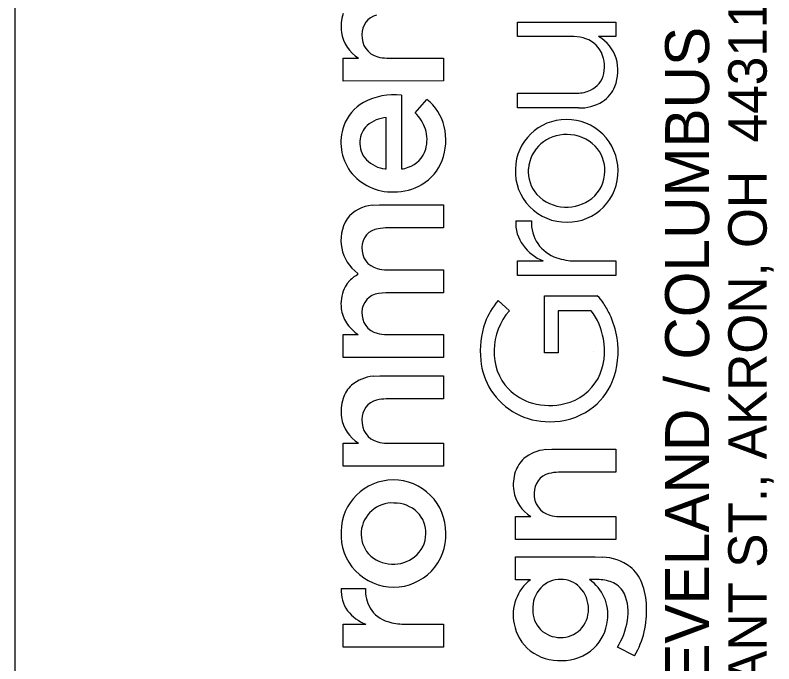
# Model space of a CAD drawing. Extents: x 0 to 70.6, y 0 to 31.9.
# Drawn here: x 32 to 32.984, y 3.594 to 4.436 of the extents above; entities that cross this region are included whole.
import ezdxf

# ---------------------------------------------------------------- set-up
doc = ezdxf.new("R2010")
doc.units = 0
doc.layers.add('GM_X_County', color=7, linetype='Continuous')
doc.layers.add('GM_X_Township', color=7, linetype='Continuous')

msp = doc.modelspace()

# ---------------------------------------------------------------- linework, layer by layer
at = {"layer": 'GM_X_County'}
msp.add_line((32, 0.5), (32, 21.5), dxfattribs=at)
at = {"layer": 'GM_X_Township'}
for p, q in [((32.65152, 4.40801), (32.65153, 4.42672)), ((32.65153, 4.42672), (32.7791, 4.42664)), ((32.7791, 4.42664), (32.77908, 4.40796)), ((32.7249, 4.40796), (32.65152, 4.40801)), ((32.7328, 4.40727), (32.7249, 4.40796)), ((32.77908, 4.40796), (32.75689, 4.40796)), ((32.42542, 4.38016), (32.44552, 4.38021)), ((32.42542, 4.35035), (32.42542, 4.38016)), ((32.48222, 4.38021), (32.55569, 4.38021)), ((32.55569, 4.38021), (32.55571, 4.35045)), ((32.55571, 4.35045), (32.42542, 4.35035)), ((32.50108, 4.33209), (32.50118, 4.23657)), ((32.65154, 4.33443), (32.72905, 4.3345)), ((32.65165, 4.31543), (32.65154, 4.33443)), ((32.51882, 4.30927), (32.53422, 4.32662)), ((32.73073, 4.31543), (32.65165, 4.31543)), ((32.48144, 4.23644), (32.48144, 4.30296)), ((32.48016, 4.23628), (32.48144, 4.23644)), ((32.46329, 4.18915), (32.47259, 4.18968)), ((32.47259, 4.18968), (32.55557, 4.18968)), ((32.55557, 4.18968), (32.55571, 4.15982)), ((32.64932, 4.16907), (32.66978, 4.16907)), ((32.48058, 4.15981), (32.47102, 4.15881)), ((32.55571, 4.15982), (32.48058, 4.15981)), ((32.65152, 4.11699), (32.68476, 4.117)), ((32.65152, 4.098), (32.65152, 4.11699)), ((32.72605, 4.11703), (32.7791, 4.11696)), ((32.7791, 4.11696), (32.77903, 4.098)), ((32.48218, 4.10553), (32.55571, 4.10548)), ((32.55571, 4.10548), (32.55571, 4.07568)), ((32.44443, 4.09922), (32.44455, 4.10072)), ((32.77903, 4.098), (32.65152, 4.098)), ((32.4809, 4.07567), (32.47143, 4.07474)), ((32.55571, 4.07568), (32.4809, 4.07567)), ((32.62636, 4.06548), (32.64114, 4.05241)), ((32.6868, 4.07185), (32.75516, 4.07192)), ((32.6868, 3.99778), (32.6868, 4.07185)), ((32.70448, 4.05241), (32.70432, 3.99775)), ((32.74737, 4.05227), (32.70448, 4.05241)), ((32.42542, 3.99152), (32.42545, 4.02138)), ((32.42545, 4.02138), (32.44515, 4.02138)), ((32.48206, 4.02138), (32.55571, 4.02136)), ((32.55571, 4.02136), (32.55571, 3.99156)), ((32.70432, 3.99775), (32.6868, 3.99778)), ((32.75, 4), (32.75, 4)), ((32.55571, 3.99156), (32.42542, 3.99152)), ((32.46439, 3.96736), (32.47289, 3.96783)), ((32.47289, 3.96783), (32.55571, 3.96783)), ((32.55571, 3.96783), (32.55571, 3.93804)), ((32.55571, 3.93804), (32.4814, 3.93796)), ((32.42542, 3.88066), (32.44552, 3.88071)), ((32.42542, 3.85086), (32.42542, 3.88066)), ((32.48222, 3.88071), (32.55569, 3.88071)), ((32.55569, 3.88071), (32.55571, 3.85096)), ((32.68784, 3.8722), (32.69634, 3.87266)), ((32.69634, 3.87266), (32.77916, 3.87266)), ((32.77916, 3.87266), (32.77917, 3.84287)), ((32.55571, 3.85096), (32.42542, 3.85086)), ((32.77917, 3.84287), (32.70485, 3.8428)), ((32.64888, 3.7855), (32.66897, 3.78555)), ((32.64888, 3.75569), (32.64888, 3.7855)), ((32.70568, 3.78555), (32.77915, 3.78555)), ((32.77915, 3.78555), (32.77917, 3.75579)), ((32.77917, 3.75579), (32.64888, 3.75569)), ((32.6489, 3.70336), (32.64889, 3.73322)), ((32.64889, 3.73322), (32.75236, 3.73322)), ((32.75236, 3.73322), (32.76191, 3.73285)), ((32.66836, 3.70336), (32.6489, 3.70336)), ((32.75763, 3.70356), (32.74487, 3.70361)), ((32.42299, 3.69193), (32.45454, 3.69193)), ((32.42542, 3.64577), (32.45473, 3.64579)), ((32.42542, 3.61593), (32.42542, 3.64577)), ((32.50413, 3.64581), (32.55571, 3.64573)), ((32.55571, 3.64573), (32.55565, 3.61593)), ((32.55565, 3.61593), (32.42542, 3.61593)), ((32.8036, 3.60491), (32.7812, 3.61598))]:
    msp.add_line(p, q, dxfattribs=at)
for points in [[(32.7328, 4.40727), (32.7249, 4.40796), (32.65152, 4.40801), (32.65153, 4.42672), (32.7791, 4.42664), (32.77908, 4.40796), (32.75689, 4.40796)], [(32.42542, 4.35035), (32.42542, 4.38016), (32.44552, 4.38021)], [(32.48222, 4.38021), (32.55569, 4.38021), (32.55571, 4.35045), (32.42542, 4.35035)], [(32.50108, 4.33209), (32.50118, 4.23657)], [(32.73073, 4.31543), (32.65165, 4.31543), (32.65154, 4.33443), (32.72905, 4.3345)], [(32.51882, 4.30927), (32.53422, 4.32662)], [(32.48016, 4.23628), (32.48144, 4.23644), (32.48144, 4.30296)], [(32.46329, 4.18915), (32.47259, 4.18968), (32.55557, 4.18968), (32.55571, 4.15982), (32.48058, 4.15981), (32.47102, 4.15881)], [(32.64932, 4.16907), (32.66978, 4.16907)], [(32.72605, 4.11703), (32.7791, 4.11696), (32.77903, 4.098), (32.65152, 4.098)], [(32.65152, 4.098), (32.65152, 4.11699), (32.68476, 4.117)], [(32.48218, 4.10553), (32.55571, 4.10548), (32.55571, 4.07568), (32.4809, 4.07567), (32.47143, 4.07474)], [(32.44443, 4.09922), (32.44455, 4.10072)], [(32.62636, 4.06548), (32.64114, 4.05241)], [(32.74737, 4.05227), (32.70448, 4.05241), (32.70432, 3.99775), (32.6868, 3.99778), (32.6868, 4.07185), (32.75516, 4.07192)], [(32.42542, 3.99152), (32.42545, 4.02138), (32.44515, 4.02138)], [(32.48206, 4.02138), (32.55571, 4.02136), (32.55571, 3.99156), (32.42542, 3.99152)], [(32.46439, 3.96736), (32.47289, 3.96783), (32.55571, 3.96783), (32.55571, 3.93804), (32.4814, 3.93796)], [(32.42542, 3.85086), (32.42542, 3.88066), (32.44552, 3.88071)], [(32.48222, 3.88071), (32.55569, 3.88071), (32.55571, 3.85096), (32.42542, 3.85086)], [(32.68784, 3.8722), (32.69634, 3.87266), (32.77916, 3.87266), (32.77917, 3.84287), (32.70485, 3.8428)], [(32.64888, 3.75569), (32.64888, 3.7855), (32.66897, 3.78555)], [(32.70568, 3.78555), (32.77915, 3.78555), (32.77917, 3.75579), (32.64888, 3.75569)], [(32.66836, 3.70336), (32.6489, 3.70336), (32.64889, 3.73322), (32.75236, 3.73322), (32.76191, 3.73285)], [(32.75763, 3.70356), (32.74487, 3.70361)], [(32.42299, 3.69193), (32.45454, 3.69193)], [(32.50413, 3.64581), (32.55571, 3.64573), (32.55565, 3.61593), (32.42542, 3.61593)], [(32.42542, 3.61593), (32.42542, 3.64577), (32.45473, 3.64579)], [(32.8036, 3.60491), (32.7812, 3.61598)]]:
    msp.add_lwpolyline(points, dxfattribs=at)
for centre, radius, start, end in [((32.47872, 4.42108), 0.05602, 162.27398, 187.79173), ((32.47872, 4.42108), 0.05602, 162.27398, 187.79173), ((32.47482, 4.41155), 0.02498, 103.68683, 182.21395), ((32.47482, 4.41155), 0.02498, 103.68683, 182.21395), ((32.47027, 4.4209), 0.04763, 188.96462, 238.69865), ((32.47027, 4.4209), 0.04763, 188.96462, 238.69865), ((32.47735, 4.40846), 0.02757, 175.58441, 255.13816), ((32.47735, 4.40846), 0.02757, 175.58441, 255.13816), ((32.72711, 4.36998), 0.03772, 33.50082, 81.32954), ((32.72711, 4.36998), 0.03772, 33.50082, 81.32954), ((32.73239, 4.36485), 0.04959, 17.62209, 60.38974), ((32.73239, 4.36485), 0.04959, 17.62209, 60.38974), ((32.72414, 4.3695), 0.04048, 346.56179, 31.75389), ((32.72414, 4.3695), 0.04048, 346.56179, 31.75389), ((32.48183, 4.42235), 0.04215, 254.08913, 270.52838), ((32.48183, 4.42235), 0.04215, 254.08913, 270.52838), ((32.72343, 4.36415), 0.05838, 339.16197, 15.61485), ((32.72343, 4.36415), 0.05838, 339.16197, 15.61485), ((32.73371, 4.36616), 0.03042, 294.63214, 348.48625), ((32.73371, 4.36616), 0.03042, 294.63214, 348.48625), ((32.739, 4.35901), 0.04201, 303.10391, 338.15613), ((32.739, 4.35901), 0.04201, 303.10391, 338.15613), ((32.49176, 4.24874), 0.08387, 83.62118, 118.28448), ((32.49176, 4.24874), 0.08387, 83.62118, 118.28448), ((32.72747, 4.38081), 0.04633, 271.95199, 294.08943), ((32.72747, 4.38081), 0.04633, 271.95199, 294.08943), ((32.47894, 4.27368), 0.05583, 118.82935, 160.62242), ((32.47894, 4.27368), 0.05583, 118.82935, 160.62242), ((32.49399, 4.2763), 0.06443, 13.53275, 51.36266), ((32.49399, 4.2763), 0.06443, 13.53275, 51.36266), ((32.7321, 4.37256), 0.05715, 268.62699, 301.47779), ((32.7321, 4.37256), 0.05715, 268.62699, 301.47779), ((32.4844, 4.26071), 0.04236, 94.01311, 130.88062), ((32.4844, 4.26071), 0.04236, 94.01311, 130.88062), ((32.48033, 4.27018), 0.05485, 19.0387, 45.44322), ((32.48033, 4.27018), 0.05485, 19.0387, 45.44322), ((32.48697, 4.27074), 0.06438, 160.52138, 215.78155), ((32.48697, 4.27074), 0.06438, 160.52138, 215.78155), ((32.47703, 4.2709), 0.02985, 132.98553, 177.1802), ((32.47703, 4.2709), 0.02985, 132.98553, 177.1802), ((32.48289, 4.27384), 0.0758, 339.35431, 13.37708), ((32.48289, 4.27384), 0.0758, 339.35431, 13.37708), ((32.71435, 4.23484), 0.06552, 89.48213, 178.77752), ((32.71435, 4.23484), 0.06552, 89.48213, 178.77752), ((32.71582, 4.23414), 0.06623, 0.42265, 90.7613), ((32.71582, 4.23414), 0.06623, 0.42265, 90.7613), ((32.48724, 4.27433), 0.04701, 344.60723, 17.00675), ((32.48724, 4.27433), 0.04701, 344.60723, 17.00675), ((32.47824, 4.26966), 0.03114, 175.00138, 223.2876), ((32.47824, 4.26966), 0.03114, 175.00138, 223.2876), ((32.71397, 4.23244), 0.04846, 87.68827, 175.01696), ((32.71397, 4.23244), 0.04846, 87.68827, 175.01696), ((32.71659, 4.23036), 0.05052, 44.91202, 90.75914), ((32.71659, 4.23036), 0.05052, 44.91202, 90.75914), ((32.49895, 4.27177), 0.03504, 288.01084, 343.55364), ((32.49895, 4.27177), 0.03504, 288.01084, 343.55364), ((32.71955, 4.23452), 0.04549, 358.32279, 43.83486), ((32.71955, 4.23452), 0.04549, 358.32279, 43.83486), ((32.48546, 4.27826), 0.04232, 225.06454, 262.79701), ((32.48546, 4.27826), 0.04232, 225.06454, 262.79701), ((32.49548, 4.26982), 0.0626, 300.94393, 338.73223), ((32.49548, 4.26982), 0.0626, 300.94393, 338.73223), ((32.48908, 4.27516), 0.06872, 217.74341, 271.65606), ((32.48908, 4.27516), 0.06872, 217.74341, 271.65606), ((32.50129, 4.25678), 0.02021, 269.70042, 294.87295), ((32.50129, 4.25678), 0.02021, 269.70042, 294.87295), ((32.71483, 4.2334), 0.06606, 177.53728, 270.94524), ((32.71483, 4.2334), 0.06606, 177.53728, 270.94524), ((32.71085, 4.23311), 0.0453, 175.51467, 221.42047), ((32.71085, 4.23311), 0.0453, 175.51467, 221.42047), ((32.71671, 4.23271), 0.06536, 269.30834, 1.67905), ((32.71671, 4.23271), 0.06536, 269.30834, 1.67905), ((32.71931, 4.23374), 0.04572, 308.90382, 359.30947), ((32.71931, 4.23374), 0.04572, 308.90382, 359.30947), ((32.49204, 4.27702), 0.07055, 269.20529, 300.33566), ((32.49204, 4.27702), 0.07055, 269.20529, 300.33566), ((32.71399, 4.23734), 0.05046, 222.66255, 268.37331), ((32.71399, 4.23734), 0.05046, 222.66255, 268.37331), ((32.71567, 4.23859), 0.05178, 266.55312, 308.67253), ((32.71567, 4.23859), 0.05178, 266.55312, 308.67253), ((32.46638, 4.14404), 0.04521, 93.91118, 142.30723), ((32.46638, 4.14404), 0.04521, 93.91118, 142.30723), ((32.47585, 4.14373), 0.05319, 148.28793, 233.9556), ((32.47585, 4.14373), 0.05319, 148.28793, 233.9556), ((32.69878, 4.16662), 0.04952, 177.16211, 216.28024), ((32.69878, 4.16662), 0.04952, 177.16211, 216.28024), ((32.71735, 4.16638), 0.04764, 176.76988, 252.15044), ((32.71735, 4.16638), 0.04764, 176.76988, 252.15044), ((32.47384, 4.13499), 0.02399, 96.75763, 181.6251), ((32.47384, 4.13499), 0.02399, 96.75763, 181.6251), ((32.47577, 4.13241), 0.02597, 175.81573, 256.16716), ((32.47577, 4.13241), 0.02597, 175.81573, 256.16716), ((32.70975, 4.17555), 0.06366, 216.91526, 246.88619), ((32.70975, 4.17555), 0.06366, 216.91526, 246.88619), ((32.7269, 4.19175), 0.07473, 251.13884, 269.34694), ((32.7269, 4.19175), 0.07473, 251.13884, 269.34694), ((32.4817, 4.15053), 0.04501, 254.34629, 270.61033), ((32.4817, 4.15053), 0.04501, 254.34629, 270.61033), ((32.4638, 4.06267), 0.04137, 117.91625, 139.24296), ((32.4638, 4.06267), 0.04137, 117.91625, 139.24296), ((32.46194, 4.06452), 0.03875, 139.52447, 154.84698), ((32.46194, 4.06452), 0.03875, 139.52447, 154.84698), ((32.47144, 4.0612), 0.04877, 156.06382, 187.3493), ((32.47144, 4.0612), 0.04877, 156.06382, 187.3493), ((32.47421, 4.05056), 0.02434, 96.5532, 179.94902), ((32.47421, 4.05056), 0.02434, 96.5532, 179.94902), ((32.70163, 4.00187), 0.09855, 139.79476, 159.13696), ((32.70163, 4.00187), 0.09855, 139.79476, 159.13696), ((32.72498, 4.03937), 0.04438, 30.98913, 47.16099), ((32.72498, 4.03937), 0.04438, 30.98913, 47.16099), ((32.46461, 4.05974), 0.04181, 186.5579, 213.38846), ((32.46461, 4.05974), 0.04181, 186.5579, 213.38846), ((32.67091, 4.00018), 0.11106, 25.30315, 33.96179), ((32.67091, 4.00018), 0.11106, 25.30315, 33.96179), ((32.47608, 4.04863), 0.02628, 175.722, 255.78627), ((32.47608, 4.04863), 0.02628, 175.722, 255.78627), ((32.69899, 4.00079), 0.07753, 138.25804, 179.70064), ((32.69899, 4.00079), 0.07753, 138.25804, 179.70064), ((32.67889, 4.00099), 0.08556, 10.07509, 36.83189), ((32.67889, 4.00099), 0.08556, 10.07509, 36.83189), ((32.6704, 3.99987), 0.11166, 8.80339, 25.33484), ((32.6704, 3.99987), 0.11166, 8.80339, 25.33484), ((32.47886, 4.07078), 0.0598, 214.70433, 235.68724), ((32.47886, 4.07078), 0.0598, 214.70433, 235.68724), ((32.7187, 3.99968), 0.11536, 161.14379, 185.62812), ((32.7187, 3.99968), 0.11536, 161.14379, 185.62812), ((32.48195, 4.06518), 0.0438, 253.66719, 270.14979), ((32.48195, 4.06518), 0.0438, 253.66719, 270.14979), ((32.68425, 4.00057), 0.08036, 333.46689, 11.03668), ((32.68425, 4.00057), 0.08036, 333.46689, 11.03668), ((32.67564, 3.99977), 0.10649, 338.28866, 9.28548), ((32.67564, 3.99977), 0.10649, 338.28866, 9.28548), ((32.68811, 3.99732), 0.06676, 176.66577, 223.6912), ((32.68811, 3.99732), 0.06676, 176.66577, 223.6912), ((32.69336, 3.99699), 0.08987, 185.50773, 212.01294), ((32.69336, 3.99699), 0.08987, 185.50773, 212.01294), ((32.46871, 3.91767), 0.04988, 94.97056, 130.22484), ((32.46871, 3.91767), 0.04988, 94.97056, 130.22484), ((32.69868, 3.99547), 0.0652, 282.88151, 331.81475), ((32.69868, 3.99547), 0.0652, 282.88151, 331.81475), ((32.69835, 3.99168), 0.08241, 305.03061, 337.67573), ((32.69835, 3.99168), 0.08241, 305.03061, 337.67573), ((32.46348, 3.92602), 0.04016, 132.22383, 161.68229), ((32.46348, 3.92602), 0.04016, 132.22383, 161.68229), ((32.69211, 3.99748), 0.08908, 212.70222, 270.71399), ((32.69211, 3.99748), 0.08908, 212.70222, 270.71399), ((32.69045, 4.00011), 0.07039, 224.02147, 253.88), ((32.69045, 4.00011), 0.07039, 224.02147, 253.88), ((32.47872, 3.92158), 0.05602, 162.27398, 187.79173), ((32.47872, 3.92158), 0.05602, 162.27398, 187.79173), ((32.48108, 3.89196), 0.04601, 89.60515, 105.33026), ((32.48108, 3.89196), 0.04601, 89.60515, 105.33026), ((32.47482, 3.91206), 0.02498, 103.68683, 182.21395), ((32.47482, 3.91206), 0.02498, 103.68683, 182.21395), ((32.69318, 4.01254), 0.08309, 254.45353, 283.9512), ((32.69318, 4.01254), 0.08309, 254.45353, 283.9512), ((32.69429, 3.99979), 0.09138, 269.3273, 304.19632), ((32.69429, 3.99979), 0.09138, 269.3273, 304.19632), ((32.47027, 3.92141), 0.04763, 188.96462, 238.69865), ((32.47027, 3.92141), 0.04763, 188.96462, 238.69865), ((32.47735, 3.90897), 0.02757, 175.58441, 255.13816), ((32.47735, 3.90897), 0.02757, 175.58441, 255.13816), ((32.48183, 3.92286), 0.04215, 254.08913, 270.52838), ((32.48183, 3.92286), 0.04215, 254.08913, 270.52838), ((32.69216, 3.82251), 0.04988, 94.97056, 130.22484), ((32.69216, 3.82251), 0.04988, 94.97056, 130.22484), ((32.68694, 3.83085), 0.04016, 132.22383, 161.68229), ((32.68694, 3.83085), 0.04016, 132.22383, 161.68229), ((32.70217, 3.82642), 0.05602, 162.27398, 187.79173), ((32.70217, 3.82642), 0.05602, 162.27398, 187.79173), ((32.69828, 3.81689), 0.02498, 103.68683, 182.21395), ((32.69828, 3.81689), 0.02498, 103.68683, 182.21395), ((32.70453, 3.79679), 0.04601, 89.60515, 105.33026), ((32.70453, 3.79679), 0.04601, 89.60515, 105.33026), ((32.49014, 3.76543), 0.0674, 89.84756, 179.64047), ((32.49014, 3.76543), 0.0674, 89.84756, 179.64047), ((32.49057, 3.76474), 0.0681, 359.54009, 90.21138), ((32.49057, 3.76474), 0.0681, 359.54009, 90.21138), ((32.69372, 3.82624), 0.04763, 188.96462, 238.69865), ((32.69372, 3.82624), 0.04763, 188.96462, 238.69865), ((32.7008, 3.81381), 0.02757, 175.58441, 255.13816), ((32.7008, 3.81381), 0.02757, 175.58441, 255.13816), ((32.48923, 3.76263), 0.0404, 87.04809, 175.57259), ((32.48923, 3.76263), 0.0404, 87.04809, 175.57259), ((32.49204, 3.75999), 0.04299, 45.84264, 90.98008), ((32.49204, 3.75999), 0.04299, 45.84264, 90.98008), ((32.49458, 3.76421), 0.03821, 357.88569, 44.15902), ((32.49458, 3.76421), 0.03821, 357.88569, 44.15902), ((32.70529, 3.82769), 0.04215, 254.08913, 270.52838), ((32.70529, 3.82769), 0.04215, 254.08913, 270.52838), ((32.49083, 3.76209), 0.06819, 176.8344, 270.40384), ((32.49083, 3.76209), 0.06819, 176.8344, 270.40384), ((32.48729, 3.7625), 0.03848, 175.15378, 221.14706), ((32.48729, 3.7625), 0.03848, 175.15378, 221.14706), ((32.49123, 3.76139), 0.06749, 270.06243, 2.37759), ((32.49123, 3.76139), 0.06749, 270.06243, 2.37759), ((32.49446, 3.76318), 0.0383, 308.28936, 359.43468), ((32.49446, 3.76318), 0.0383, 308.28936, 359.43468), ((32.48919, 3.76607), 0.04228, 223.09994, 268.80895), ((32.48919, 3.76607), 0.04228, 223.09994, 268.80895), ((32.49096, 3.7679), 0.04418, 266.56515, 308.06078), ((32.49096, 3.7679), 0.04418, 266.56515, 308.06078), ((32.75907, 3.66789), 0.06503, 53.40344, 87.49062), ((32.75907, 3.66789), 0.06503, 53.40344, 87.49062), ((32.76517, 3.68039), 0.05141, 21.60748, 50.5577), ((32.76517, 3.68039), 0.05141, 21.60748, 50.5577), ((32.70292, 3.65813), 0.05692, 127.37482, 192.22468), ((32.70292, 3.65813), 0.05692, 127.37482, 192.22468), ((32.70693, 3.66927), 0.0346, 88.47302, 136.42562), ((32.70693, 3.66927), 0.0346, 88.47302, 136.42562), ((32.70814, 3.66963), 0.03424, 44.27195, 90.47623), ((32.70814, 3.66963), 0.03424, 44.27195, 90.47623), ((32.71421, 3.65829), 0.05472, 352.1125, 55.92295), ((32.71421, 3.65829), 0.05472, 352.1125, 55.92295), ((32.75666, 3.65725), 0.04633, 65.01687, 88.8011), ((32.75666, 3.65725), 0.04633, 65.01687, 88.8011), ((32.46616, 3.68882), 0.04329, 175.87313, 216.34747), ((32.46616, 3.68882), 0.04329, 175.87313, 216.34747), ((32.50087, 3.68948), 0.04639, 176.9688, 209.60636), ((32.50087, 3.68948), 0.04639, 176.9688, 209.60636), ((32.71141, 3.66602), 0.0401, 137.46739, 182.33237), ((32.71141, 3.66602), 0.0401, 137.46739, 182.33237), ((32.70368, 3.666), 0.03996, 358.57141, 43.53765), ((32.70368, 3.666), 0.03996, 358.57141, 43.53765), ((32.7626, 3.67155), 0.03085, 26.26808, 63.80301), ((32.7626, 3.67155), 0.03085, 26.26808, 63.80301), ((32.73069, 3.66714), 0.08835, 1.15143, 21.3627), ((32.73069, 3.66714), 0.08835, 1.15143, 21.3627), ((32.73565, 3.66154), 0.05953, 349.30734, 23.43071), ((32.73565, 3.66154), 0.05953, 349.30734, 23.43071), ((32.47466, 3.69716), 0.05511, 218.09809, 248.7907), ((32.47466, 3.69716), 0.05511, 218.09809, 248.7907), ((32.49514, 3.68814), 0.04079, 211.94466, 253.2028), ((32.49514, 3.68814), 0.04079, 211.94466, 253.2028), ((32.70645, 3.6637), 0.03511, 178.88208, 271.08374), ((32.70645, 3.6637), 0.03511, 178.88208, 271.08374), ((32.70818, 3.66404), 0.03546, 268.27882, 1.55016), ((32.70818, 3.66404), 0.03546, 268.27882, 1.55016), ((32.70538, 3.66244), 0.11383, 329.6388, 3.25998), ((32.70538, 3.66244), 0.11383, 329.6388, 3.25998), ((32.50465, 3.7165), 0.07069, 252.46555, 269.57296), ((32.50465, 3.7165), 0.07069, 252.46555, 269.57296), ((32.70463, 3.65696), 0.05837, 190.75182, 231.28919), ((32.70463, 3.65696), 0.05837, 190.75182, 231.28919), ((32.70988, 3.65708), 0.05887, 313.74196, 353.8554), ((32.70988, 3.65708), 0.05887, 313.74196, 353.8554), ((32.70738, 3.66334), 0.08771, 327.31495, 351.57478), ((32.70738, 3.66334), 0.08771, 327.31495, 351.57478), ((32.70954, 3.65901), 0.06051, 269.6361, 312.70877), ((32.70954, 3.65901), 0.06051, 269.6361, 312.70877), ((32.70632, 3.66112), 0.06269, 232.46061, 272.59022), ((32.70632, 3.66112), 0.06269, 232.46061, 272.59022)]:
    msp.add_arc(centre, radius, start, end, dxfattribs=at)

# ---------------------------------------------------------------- texts
for s, height, p in [('450 GRANT ST., AKRON, OH  44311', 0.0498462, (32.97489, 3.33738)), ('AKRON / CLEVELAND / COLUMBUS', 0.056969, (32.90012, 3.138))]:
    msp.add_text(s, height=height, rotation=90, dxfattribs=at).set_placement(p)

doc.saveas('drawing.dxf')
